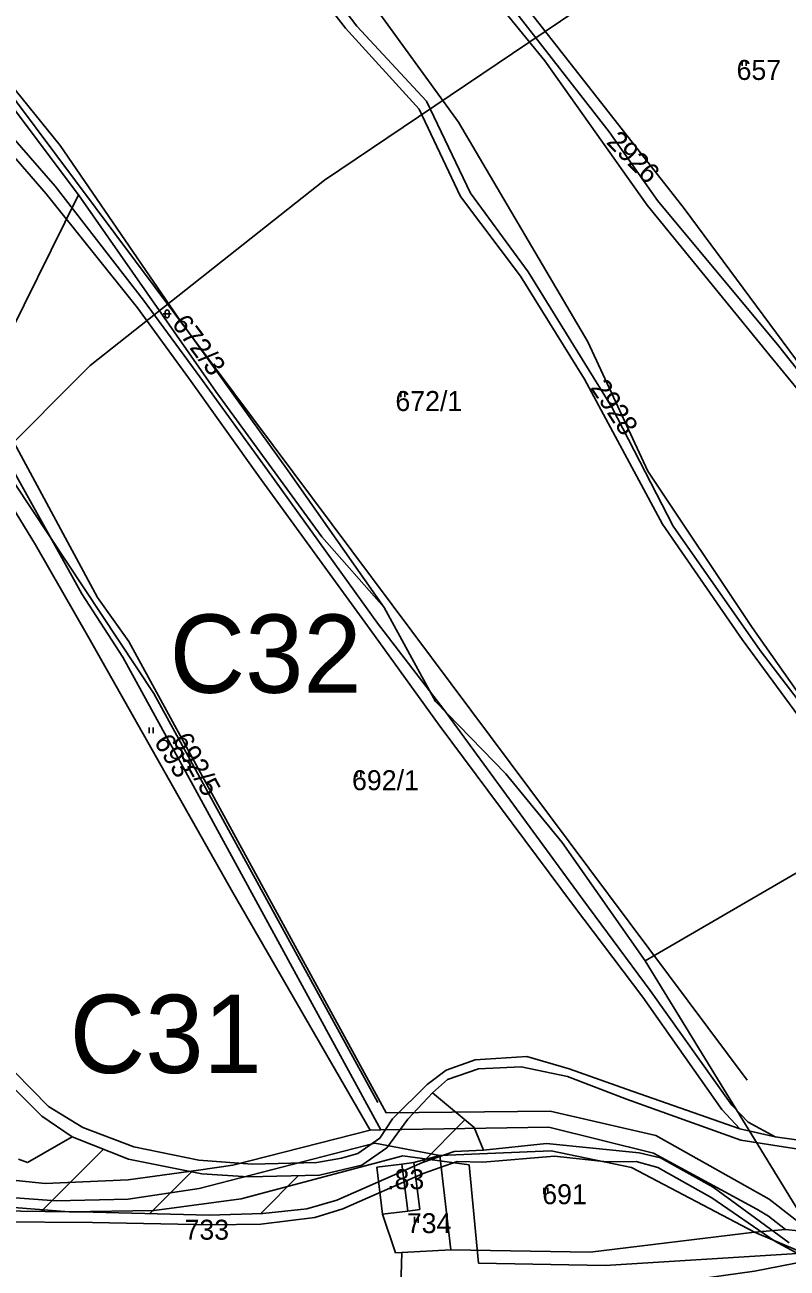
# Model space of a CAD drawing. Extents: x -564810 to -550519, y -1045831 to -1034011.
# Drawn here: x -554486 to -554291.4, y -1037713.3 to -1037395.7 of the extents above; entities that cross this region are included whole.
import ezdxf

# ---------------------------------------------------------------- set-up
doc = ezdxf.new("R2010")
doc.units = 0
for name, color, linetype in [('Interakční prvky', 7, 'Continuous'), ('KN stav', 7, 'Continuous'), ('Lesní porost', 7, 'Continuous'), ('Obvod KPU', 7, 'Continuous'), ('označ pol cest', 7, 'Continuous'), ('Parcelní čísla', 7, 'Continuous'), ('Polní cesty stavající', 7, 'Continuous'), ('STG', 7, 'Continuous'), ('Vrstva 16', 7, 'Continuous'), ('Vrstva 22', 7, 'Continuous'), ('Vrstva 4', 7, 'Continuous'), ('zamokř ploch', 7, 'Continuous')]:
    doc.layers.add(name, color=color, linetype=linetype)

msp = doc.modelspace()

# ---------------------------------------------------------------- linework, layer by layer
at = {"layer": 'Interakční prvky'}
for p, q in [((-554468.39, -1037250.34), (-554317.66, -1037442.66)), ((-554375.29, -1037420.6), (-554476.05, -1037281.3)), ((-554499.83, -1037399.84), (-554301.54, -1037665.3)), ((-554342.24, -1037476.65), (-554375.29, -1037420.6)), ((-554546.17, -1037426.21), (-554453.08, -1037566.52)), ((-554317.66, -1037442.66), (-554208.04, -1037590.75)), ((-554326.93, -1037509.71), (-554342.24, -1037476.65)), ((-554300.33, -1037549.62), (-554326.93, -1037509.71)), ((-554239.07, -1037636.71), (-554300.33, -1037549.62)), ((-554453.08, -1037566.52), (-554395.85, -1037670.94))]:
    msp.add_line(p, q, dxfattribs=at)
at = {"layer": 'KN stav'}
for p, q in [((-554532.67, -1037357.98), (-554476.99, -1037426.53)), ((-554401.24, -1037396.09), (-554431.15, -1037356.3)), ((-554424.35, -1037370.19), (-554404.19, -1037396.54)), ((-554379.98, -1037371.95), (-554353.25, -1037404.87)), ((-554336.8, -1037423.06), (-554374.62, -1037374.57)), ((-554404.19, -1037396.54), (-554385.34, -1037417.28)), ((-554383.44, -1037415.21), (-554401.24, -1037396.09)), ((-554353.25, -1037404.87), (-554327.08, -1037441.74)), ((-554372.22, -1037438.72), (-554383.44, -1037415.21)), ((-554472.3, -1037439.11), (-554488.78, -1037417.27)), ((-554385.34, -1037417.28), (-554374.76, -1037439.58)), ((-554324.49, -1037440.58), (-554336.8, -1037423.06)), ((-554476.99, -1037426.53), (-554446.93, -1037470.35)), ((-554472.3, -1037439.11), (-554497.88, -1037490.73)), ((-554437.29, -1037489.35), (-554472.3, -1037439.11)), ((-554374.76, -1037439.58), (-554359.48, -1037459.91)), ((-554357.47, -1037458.79), (-554372.22, -1037438.72)), ((-554293.47, -1037477.81), (-554324.49, -1037440.58)), ((-554327.08, -1037441.74), (-554295.79, -1037480.16)), ((-554359.48, -1037459.91), (-554343.15, -1037486.22)), ((-554336.11, -1037493.37), (-554357.47, -1037458.79)), ((-554446.93, -1037470.35), (-554418.79, -1037509.59)), ((-554266.14, -1037512.41), (-554293.47, -1037477.81)), ((-554295.79, -1037480.16), (-554266.94, -1037515.49)), ((-554343.15, -1037486.22), (-554323.2, -1037523.28)), ((-554410.15, -1037526.5), (-554437.29, -1037489.35)), ((-554320.43, -1037523.74), (-554336.11, -1037493.37)), ((-554495.41, -1037498.04), (-554471.49, -1037541.05)), ((-554491.76, -1037496.96), (-554467.46, -1037541.95)), ((-554500.01, -1037501.28), (-554483.28, -1037528.55)), ((-554418.79, -1037509.59), (-554394.28, -1037544.53)), ((-554323.2, -1037523.28), (-554302.81, -1037552.71)), ((-554298.22, -1037555.55), (-554320.43, -1037523.74)), ((-554394.28, -1037544.53), (-554410.15, -1037526.5)), ((-554483.28, -1037528.55), (-554469.69, -1037552.3)), ((-554471.49, -1037541.05), (-554460.98, -1037557.19)), ((-554467.46, -1037541.95), (-554459.48, -1037553.22)), ((-554381.15, -1037568.53), (-554394.28, -1037544.53)), ((-554469.69, -1037552.3), (-554432.95, -1037617.32)), ((-554302.81, -1037552.71), (-554268.19, -1037599.99)), ((-554459.48, -1037553.22), (-554393.74, -1037673.58)), ((-554272.12, -1037589.81), (-554298.22, -1037555.55)), ((-554460.98, -1037557.19), (-554443.01, -1037590.02)), ((-554363.22, -1037587.03), (-554381.15, -1037568.53)), ((-554348.81, -1037604.55), (-554363.22, -1037587.03)), ((-554443.01, -1037590.02), (-554395.13, -1037677.94)), ((-554271.62, -1037602.17), (-554327.63, -1037634.79)), ((-554327.63, -1037634.79), (-554348.81, -1037604.55)), ((-554432.95, -1037617.32), (-554397.85, -1037678)), ((-554327.63, -1037634.79), (-554285.1, -1037704.08)), ((-554393.74, -1037673.58), (-554351.87, -1037673.22)), ((-554351.87, -1037673.22), (-554324.86, -1037679.43)), ((-554432.88, -1037686.94), (-554397.85, -1037678)), ((-554397.85, -1037678), (-554395.13, -1037677.94)), ((-554395.13, -1037677.94), (-554352.22, -1037677.23)), ((-554352.22, -1037677.23), (-554325.46, -1037683.9)), ((-554324.86, -1037679.43), (-554295.91, -1037695.62)), ((-554396.62, -1037681.32), (-554441.52, -1037692.96)), ((-554380.06, -1037684.51), (-554396.62, -1037681.32)), ((-554380.06, -1037684.51), (-554386.66, -1037686.32)), ((-554351.63, -1037683.31), (-554380.06, -1037684.51)), ((-554380.06, -1037684.51), (-554377.23, -1037708.62)), ((-554331.14, -1037687.61), (-554351.63, -1037683.31)), ((-554325.46, -1037683.9), (-554299.07, -1037698.2)), ((-554459.61, -1037690.75), (-554441.66, -1037688.26)), ((-554441.66, -1037688.26), (-554432.88, -1037686.94)), ((-554389.72, -1037686.7), (-554396.15, -1037687.51)), ((-554396.15, -1037687.51), (-554394.66, -1037699.48)), ((-554386.66, -1037686.32), (-554389.72, -1037686.7)), ((-554386.66, -1037686.32), (-554385.17, -1037698.3)), ((-554299.71, -1037704.12), (-554331.14, -1037687.61)), ((-554495.12, -1037690.22), (-554480.84, -1037691.67)), ((-554480.84, -1037691.67), (-554459.61, -1037690.75)), ((-554478.01, -1037696.07), (-554504.83, -1037694.1)), ((-554459.66, -1037695.62), (-554478.01, -1037696.07)), ((-554441.52, -1037692.96), (-554459.66, -1037695.62)), ((-554295.91, -1037695.62), (-554285.1, -1037704.08)), ((-554388.22, -1037698.68), (-554394.66, -1037699.48)), ((-554385.17, -1037698.3), (-554388.22, -1037698.68)), ((-554299.07, -1037698.2), (-554296.12, -1037699.99)), ((-554394.66, -1037699.48), (-554391.39, -1037709.4)), ((-554296.12, -1037699.99), (-554291.75, -1037703.43)), ((-554341.67, -1037709.18), (-554299.71, -1037704.12)), ((-554299.71, -1037704.12), (-554291.75, -1037703.43)), ((-554291.75, -1037703.43), (-554299.71, -1037704.12)), ((-554255, -1037723.1), (-554299.71, -1037704.12)), ((-554299.71, -1037704.12), (-554255, -1037723.1)), ((-554291.75, -1037703.43), (-554285.1, -1037704.08)), ((-554285.1, -1037704.08), (-554291.75, -1037703.43)), ((-554391.39, -1037709.4), (-554389.74, -1037709.27)), ((-554389.74, -1037709.27), (-554389.99, -1037718.03)), ((-554377.23, -1037708.62), (-554389.74, -1037709.27)), ((-554377.23, -1037708.62), (-554341.67, -1037709.18))]:
    msp.add_line(p, q, dxfattribs=at)
at = {"layer": 'Lesní porost'}
for p, q in [((-554381.95, -1037668.52), (-554388.27, -1037675.2)), ((-554371.33, -1037677.32), (-554381.95, -1037668.52)), ((-554388.27, -1037675.2), (-554393.59, -1037682.52)), ((-554384.48, -1037686.26), (-554373.63, -1037675.41)), ((-554473.92, -1037679.76), (-554485.36, -1037686.25)), ((-554459.58, -1037685.46), (-554473.92, -1037679.76)), ((-554368.88, -1037683.1), (-554371.33, -1037677.32)), ((-554481.87, -1037698.79), (-554465.99, -1037682.91)), ((-554393.59, -1037682.52), (-554400, -1037686.97)), ((-554485.36, -1037686.25), (-554487.68, -1037685.46)), ((-554440.88, -1037689.15), (-554459.58, -1037685.46)), ((-554384.52, -1037686.27), (-554376.36, -1037683.49)), ((-554376.36, -1037683.49), (-554368.88, -1037683.1)), ((-554454.17, -1037699.38), (-554443.44, -1037688.65)), ((-554428.89, -1037689.91), (-554440.88, -1037689.15)), ((-554400, -1037686.97), (-554410.76, -1037689.5)), ((-554406.39, -1037695.91), (-554384.52, -1037686.27)), ((-554410.76, -1037689.5), (-554428.89, -1037689.91)), ((-554425.81, -1037699.3), (-554416.13, -1037689.62)), ((-554494.43, -1037698.58), (-554468.62, -1037699.01)), ((-554425.27, -1037699.28), (-554414.05, -1037698.11)), ((-554414.05, -1037698.11), (-554406.39, -1037695.91)), ((-554468.62, -1037699.01), (-554438.98, -1037699.77)), ((-554438.98, -1037699.77), (-554425.27, -1037699.28))]:
    msp.add_line(p, q, dxfattribs=at)
at = {"layer": 'Obvod KPU'}
for p, q in [((-554430.79, -1037695.56), (-554389.48, -1037684.57)), ((-554389.48, -1037684.57), (-554372.58, -1037686.88)), ((-554372.58, -1037686.88), (-554370.22, -1037711.99)), ((-554453.05, -1037698.58), (-554430.79, -1037695.56)), ((-554497.11, -1037697.13), (-554474.68, -1037698.91)), ((-554474.68, -1037698.91), (-554453.05, -1037698.58)), ((-554337.84, -1037712.64), (-554288.75, -1037709.51)), ((-554370.22, -1037711.99), (-554337.84, -1037712.64))]:
    msp.add_line(p, q, dxfattribs=at)
at = {"layer": 'Polní cesty stavající'}
for p, q in [((-554508.76, -1037406.28), (-554480.62, -1037438.92)), ((-554478.31, -1037436.93), (-554506.37, -1037404.72)), ((-554455.7, -1037466.07), (-554478.31, -1037436.93)), ((-554480.62, -1037438.92), (-554457.27, -1037467.97)), ((-554441.38, -1037485.6), (-554455.7, -1037466.07)), ((-554457.27, -1037467.97), (-554443.53, -1037486.83)), ((-554424.08, -1037509.46), (-554441.38, -1037485.6)), ((-554443.53, -1037486.83), (-554426.21, -1037511.13)), ((-554426.21, -1037511.13), (-554397.89, -1037550.14)), ((-554396.01, -1037548.54), (-554424.08, -1037509.46)), ((-554379.07, -1037570.63), (-554396.01, -1037548.54)), ((-554397.89, -1037550.14), (-554380.23, -1037574.57)), ((-554343.51, -1037619.12), (-554379.07, -1037570.63)), ((-554380.23, -1037574.57), (-554345.89, -1037620.66)), ((-554326.31, -1037642.35), (-554343.51, -1037619.12)), ((-554345.89, -1037620.66), (-554328.21, -1037644.06)), ((-554328.21, -1037644.06), (-554308.07, -1037672.74)), ((-554305.46, -1037671.64), (-554326.31, -1037642.35)), ((-554479.96, -1037672.01), (-554492.93, -1037658.89)), ((-554371.02, -1037660.11), (-554378.4, -1037662.75)), ((-554357.85, -1037659.23), (-554371.02, -1037660.11)), ((-554347.03, -1037662.33), (-554357.85, -1037659.23)), ((-554495.15, -1037661.03), (-554481.74, -1037674.42)), ((-554378.4, -1037662.75), (-554383.32, -1037666.39)), ((-554378.11, -1037665.05), (-554370.19, -1037662.39)), ((-554370.19, -1037662.39), (-554359.28, -1037661.82)), ((-554359.28, -1037661.82), (-554347.47, -1037664.35)), ((-554332.36, -1037667.56), (-554347.03, -1037662.33)), ((-554383.32, -1037666.39), (-554392.17, -1037675.1)), ((-554381.95, -1037668.52), (-554378.11, -1037665.05)), ((-554347.47, -1037664.35), (-554332.41, -1037670.1)), ((-554388.27, -1037675.2), (-554381.95, -1037668.52)), ((-554332.41, -1037670.1), (-554303.2, -1037680.56)), ((-554303.41, -1037677.66), (-554332.36, -1037667.56)), ((-554471.22, -1037677.39), (-554479.96, -1037672.01)), ((-554308.07, -1037672.74), (-554303.41, -1037677.66)), ((-554301.3, -1037675.99), (-554305.46, -1037671.64)), ((-554481.74, -1037674.42), (-554473.92, -1037679.76)), ((-554392.17, -1037675.1), (-554395.39, -1037680.08)), ((-554393.59, -1037682.52), (-554388.27, -1037675.2)), ((-554294.38, -1037679.72), (-554301.3, -1037675.99)), ((-554473.92, -1037679.76), (-554459.58, -1037685.46)), ((-554458.19, -1037682.31), (-554471.22, -1037677.39)), ((-554303.41, -1037677.66), (-554294.38, -1037679.72)), ((-554303.41, -1037677.66), (-554294.38, -1037679.72)), ((-554294.38, -1037679.72), (-554303.41, -1037677.66)), ((-554283.02, -1037681.36), (-554294.38, -1037679.72)), ((-554441.62, -1037685.71), (-554458.19, -1037682.31)), ((-554395.39, -1037680.08), (-554400.98, -1037684.01)), ((-554400, -1037686.97), (-554393.59, -1037682.52)), ((-554352.79, -1037681.47), (-554368.88, -1037683.1)), ((-554329.15, -1037683.79), (-554352.79, -1037681.47)), ((-554303.2, -1037680.56), (-554283.44, -1037683.64)), ((-554459.58, -1037685.46), (-554440.88, -1037689.15)), ((-554428.02, -1037686.71), (-554441.62, -1037685.71)), ((-554405.19, -1037685.2), (-554411.48, -1037686.26)), ((-554400.98, -1037684.01), (-554405.19, -1037685.2)), ((-554376.36, -1037683.49), (-554384.52, -1037686.27)), ((-554384.29, -1037689.06), (-554375.67, -1037686)), ((-554368.88, -1037683.1), (-554376.36, -1037683.49)), ((-554375.67, -1037686), (-554369.07, -1037686.19)), ((-554369.07, -1037686.19), (-554350.75, -1037684.7)), ((-554350.75, -1037684.7), (-554337.4, -1037686.16)), ((-554337.4, -1037686.16), (-554329.9, -1037686.06)), ((-554329.9, -1037686.06), (-554324.42, -1037687.54)), ((-554323.68, -1037685.13), (-554329.15, -1037683.79)), ((-554310.28, -1037692.55), (-554323.68, -1037685.13)), ((-554440.88, -1037689.15), (-554428.89, -1037689.91)), ((-554411.48, -1037686.26), (-554428.02, -1037686.71)), ((-554410.76, -1037689.5), (-554400, -1037686.97)), ((-554384.52, -1037686.27), (-554406.39, -1037695.91)), ((-554404.8, -1037698.12), (-554384.29, -1037689.06)), ((-554324.42, -1037687.54), (-554310.59, -1037695.3)), ((-554428.89, -1037689.91), (-554410.76, -1037689.5)), ((-554310.59, -1037695.3), (-554294.49, -1037706.4)), ((-554290.87, -1037706.84), (-554310.28, -1037692.55)), ((-554468.62, -1037699.01), (-554494.43, -1037698.58)), ((-554414.05, -1037698.11), (-554425.27, -1037699.28)), ((-554406.39, -1037695.91), (-554414.05, -1037698.11)), ((-554411.98, -1037700.36), (-554404.8, -1037698.12)), ((-554495.72, -1037701.45), (-554468.79, -1037701.58)), ((-554468.79, -1037701.58), (-554438.31, -1037702.17)), ((-554438.98, -1037699.77), (-554468.62, -1037699.01)), ((-554425.27, -1037699.28), (-554438.98, -1037699.77)), ((-554438.31, -1037702.17), (-554425.73, -1037702.01)), ((-554425.73, -1037702.01), (-554411.98, -1037700.36)), ((-554294.49, -1037706.4), (-554288.38, -1037709.72))]:
    msp.add_line(p, q, dxfattribs=at)
at = {"layer": 'STG'}
msp.add_lwpolyline([(-553755.9, -1037388.76), (-553770.59, -1037447.57), (-553770.59, -1037486.16), (-553811.01, -1037524.75), (-553882.66, -1037574.36), (-553954.3, -1037625.81), (-553980.02, -1037635), (-554031.46, -1037658.89), (-554167.41, -1037688.29), (-554299.68, -1037714.02), (-554404.39, -1037728.72), (-554477.88, -1037741.58), (-554523.8, -1037756.28), (-554578.92, -1037787.52), (-554611.99, -1037848.16), (-554634.03, -1037903.29), (-554661.59, -1037958.42), (-554678.12, -1037969.44), (-554718.54, -1038002.52), (-554762.63, -1038019.06), (-554880.2, -1038048.46), (-554951.85, -1038055.81), (-555038.19, -1038074.19)], dxfattribs=at)
at = {"layer": 'Vrstva 16'}
msp.add_lwpolyline([(-553156.59, -1036068.23), (-553271.19, -1036329.95), (-553326.01, -1036402.23), (-553438.12, -1036581.7), (-553500.41, -1036678.91), (-553537.78, -1036773.63), (-553654.88, -1036898.25), (-553794.4, -1036983), (-553946.38, -1037072.73), (-554030.85, -1037138.79), (-554140.47, -1037236), (-554172.86, -1037275.88), (-554409.55, -1037435.4), (-554469.35, -1037482.76), (-554516.68, -1037530.12), (-554559.04, -1037579.97), (-554569, -1037664.72), (-554661.19, -1037749.47), (-554907.84, -1037851.66), (-555066.31, -1037953.36)], dxfattribs=at)
at = {"layer": 'Vrstva 4'}
msp.add_line((-554389.72, -1037686.7), (-554388.22, -1037698.67), dxfattribs=at)
at = {"layer": 'zamokř ploch'}
for p, q in [((-554302.83, -1037404.73), (-554302.83, -1037406.23)), ((-554301.83, -1037404.73), (-554301.83, -1037406.23)), ((-554450.69, -1037469.55), (-554448.69, -1037469.55)), ((-554450.19, -1037470.05), (-554450.19, -1037469.05)), ((-554449.19, -1037469.05), (-554449.19, -1037470.05)), ((-554389.98, -1037489.29), (-554389.98, -1037490.79)), ((-554388.98, -1037489.29), (-554388.98, -1037490.79)), ((-554454.25, -1037575.15), (-554454.25, -1037576.65)), ((-554453.25, -1037575.15), (-554453.25, -1037576.65)), ((-554401.23, -1037586.31), (-554401.23, -1037587.81)), ((-554400.23, -1037586.31), (-554400.23, -1037587.81)), ((-554353.47, -1037692.79), (-554353.47, -1037694.29)), ((-554352.47, -1037692.79), (-554352.47, -1037694.29)), ((-554386.56, -1037700.21), (-554386.56, -1037701.71)), ((-554385.56, -1037700.21), (-554385.56, -1037701.71))]:
    msp.add_line(p, q, dxfattribs=at)
for centre, start, end in [((-554449.69, -1037469.05), 0, 180), ((-554449.69, -1037470.05), 180, 0)]:
    msp.add_arc(centre, 0.5, start, end, dxfattribs=at)

# ---------------------------------------------------------------- texts
at = {"layer": 'označ pol cest'}
for s, p in [('C32', (-554449.09, -1037566.32)), ('C31', (-554474.6, -1037663.44))]:
    msp.add_text(s, height=20, dxfattribs=at).set_placement(p)
at = {"layer": 'Parcelní čísla'}
for s, p in [('657', (-554304.27, -1037409.79)), ('672/1', (-554391.4, -1037494.35)), ('692/1', (-554402.48, -1037591.2)), ('691', (-554353.9, -1037696.94)), ('733', (-554445.26, -1037706.01)), ('734', (-554388.49, -1037704.34))]:
    msp.add_text(s, height=5.1, dxfattribs=at).set_placement(p)
for s, rotation, p in [('2926', 314.736, (-554337.74, -1037425.87)), ('672/3', 306.7374, (-554448.7, -1037472.12)), ('2928', 303.4507, (-554341.75, -1037488.4)), ('693', 302.165, (-554453.21, -1037578.89)), ('692/5', 298.6946, (-554448.44, -1037578.26))]:
    msp.add_text(s, height=5.1, rotation=rotation, dxfattribs=at).set_placement(p)
at = {"layer": 'Vrstva 22'}
msp.add_text('.83', height=5.1, dxfattribs=at).set_placement((-554393.51, -1037693.11))

doc.saveas('drawing.dxf')
